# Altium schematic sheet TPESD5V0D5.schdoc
size 127 x 101 mm
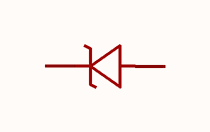
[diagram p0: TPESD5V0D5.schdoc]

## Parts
D?  tpesd5v0d5  [SOD-523_L1.2-W0.8-LS1.6-RD]  (value not drawn)

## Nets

Not connected (* = marked no-connect by the designer): D? 1(K) 2(A)

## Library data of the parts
D? = tpesd5v0d5: 反向截止电压(Vrwm):5V;钳位电压:15V；9V;峰值脉冲功率(Ppp):150W@8/20us;击穿电压:6V;; Manufacturer: TECH PUBLIC(台舟); AddInBom: yes; ModelId: 8f56a03db567494d8f4c9d12aa52a741; ModelName: SOD-523_L1.2-W0.8-H0.7-LS1.6; ModelTransform: 62.992,31.496,0,180,0,0,0,0,0; Reverse Stand-Off Voltage (Vrwm): 5V; Clamping Voltage: 15V；9V; Voltage - Breakdown: 6V; Reverse Leakage Current (Ir): 200nA; level of protection: IEC 61000-4-4；IEC 61000-4-2; Type: ESD; Junction Capacitance: 100pF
